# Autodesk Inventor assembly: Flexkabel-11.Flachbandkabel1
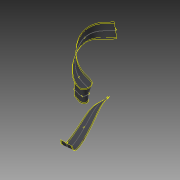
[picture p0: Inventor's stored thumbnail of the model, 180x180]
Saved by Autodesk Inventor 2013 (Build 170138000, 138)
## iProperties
Part Number: Flexkabel-11.Flachbandkabel1
Material: Allgemein
Description: Flexkabel
Part Number: Flexkabel-11.Flachbandkabel2
Created: 2012-08
Part Number: HBG-Roboter.Kabelbaum1
Document SubType Name: Assembly
Designer: rYan
ParentFileIdentifier: 5|1|0|0|22|1|0|0|80|0|65|0|84|0|72|0|83|0|59|0|69|0|58|0|92|0|84|0|105|0|103|0|101|0|114|0|115|0|32|0|83|0|86|0|78|0|92|0|109|0|101|0|99|0|104|0|97|0|110|0|105|
HarnessSettings: <HarnessSettings><Defaults><Segments><Diameter value="0.200 in" fromwires="True"/><Offset value="0.100 in"/><ColorStyle value="Blau"/><RoundUp value=""/><BendRa
Author: rYan
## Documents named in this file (2)
- D:\SVN\2013\Inventor\Kabel und Kabelbaum\HBG-Roboter.Kabelbaum1.iam
- D:\SVN\2013\Inventor\Kabel und Kabelbaum\HBG-Roboter.Kabelbaum1.ipt
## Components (3 placed, 3 different names)
1. Kabelbaum1
2. HA_VC_111:1
3. HA_VC_117:1
